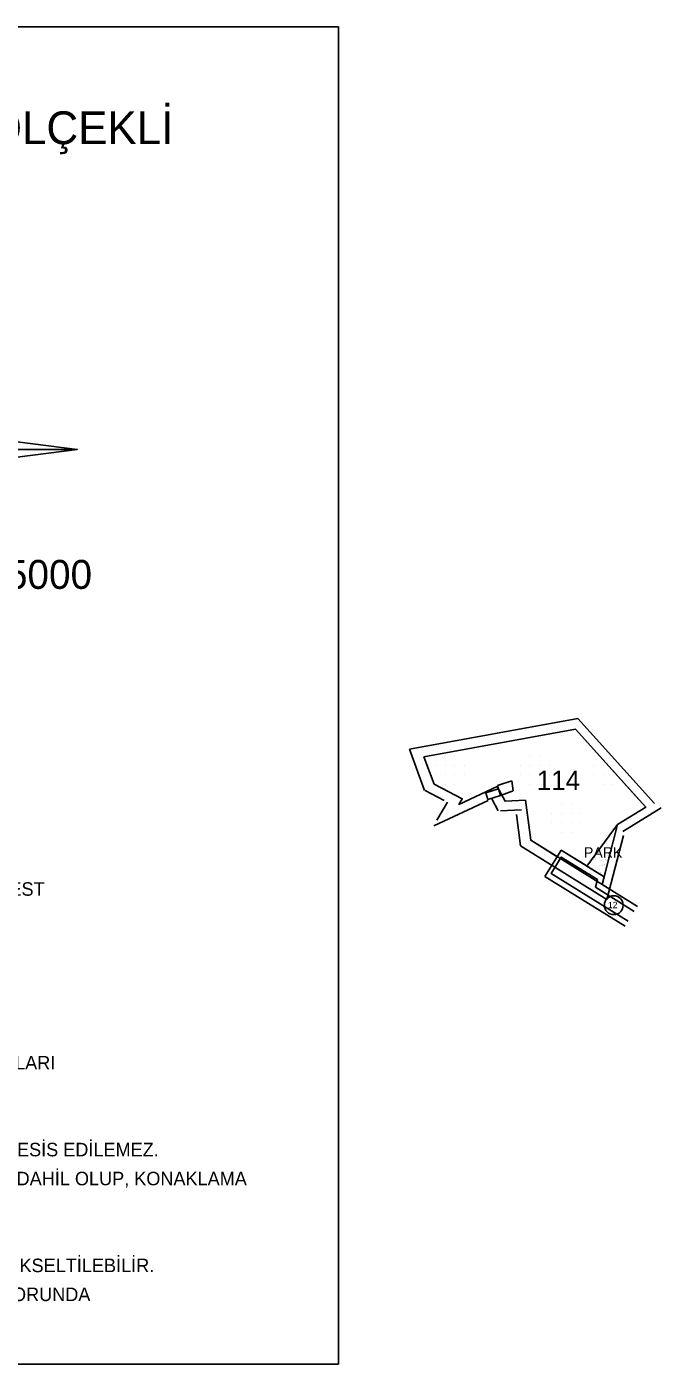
# Model space of a CAD drawing. Extents: x 415376 to 421084, y 4391163 to 4393878.
# Drawn here: x 417511 to 417839, y 4392614 to 4393307 of the extents above; entities that cross this region are included whole.
import ezdxf

# ---------------------------------------------------------------- set-up
doc = ezdxf.new("R2010")
doc.units = 0
for name, color, linetype in [('ADAKENARII', 7, 'Continuous'), ('ADAYRIMM', 7, 'Continuous'), ('KALDIRIM', 7, 'Continuous'), ('KDS_BİNA', 7, 'Continuous'), ('KDS_PARSEL', 7, 'Continuous'), ('KDS_PARSEL_NO', 7, 'Continuous'), ('LEJAND', 7, 'Continuous'), ('PL_KiRSALTURIZM', 7, 'Continuous'), ('PL_PARK', 7, 'Continuous'), ('SN_PLAN_ONAMA', 7, 'Continuous'), ('TR_PARK', 7, 'Continuous'), ('TR_TURIZM', 7, 'Continuous')]:
    doc.layers.add(name, color=color, linetype=linetype)

msp = doc.modelspace()

# ---------------------------------------------------------------- linework, layer by layer
at = {"layer": 'ADAKENARII'}
for p, q in [((417785.91, 4392877.51), (417779.06, 4392866.5)), ((417787.51, 4392880.09), (417785.91, 4392877.51)), ((417809.67, 4392866.31), (417787.51, 4392880.09)), ((417779.06, 4392866.5), (417820.57, 4392840.69)), ((417808.62, 4392862.25), (417809.67, 4392866.31)), ((417826.91, 4392850.88), (417808.62, 4392862.25))]:
    msp.add_line(p, q, dxfattribs=at)
at = {"layer": 'ADAYRIMM'}
for p, q in [((417831.32, 4392902.41), (417826.15, 4392908.13)), ((417816.67, 4392893.42), (417831.32, 4392902.41)), ((417816.67, 4392893.42), (417800.77, 4392871.84)), ((417809.67, 4392866.31), (417816.67, 4392893.42)), ((417784.45, 4392877.28), (417785.4, 4392876.69))]:
    msp.add_line(p, q, dxfattribs=at)
msp.add_lwpolyline([(417784.45, 4392877.28), (417771.71, 4392885.2), (417768.99, 4392905.94), (417758.52, 4392905.41), (417754.42, 4392913.01), (417734.58, 4392903.83), (417736.28, 4392906.74), (417721.72, 4392914.35), (417716.44, 4392928.36), (417794.85, 4392942.72), (417826.15, 4392908.13)], dxfattribs=at)
at = {"layer": 'KALDIRIM'}
msp.add_lwpolyline([(417825.33, 4392848.33), (417805.16, 4392860.87), (417806.21, 4392864.92), (417787.52, 4392876.54), (417782.24, 4392868.05), (417822.16, 4392843.23)], dxfattribs=at)
msp.add_circle((417814.69, 4392851.58), 4.87, dxfattribs=at)
at = {"layer": 'KDS_BİNA'}
for p, q in [((417754.55, 4392913.6), (417761.98, 4392915.96)), ((417755.07, 4392911.8), (417754.55, 4392913.6)), ((417761.98, 4392915.96), (417762.62, 4392910.81)), ((417755.06, 4392911.84), (417748.47, 4392909.78)), ((417748.47, 4392909.78), (417749.55, 4392906.35)), ((417749.55, 4392906.35), (417756.14, 4392908.44)), ((417756.14, 4392908.44), (417755.06, 4392911.84)), ((417762.62, 4392910.81), (417756.14, 4392908.44))]:
    msp.add_line(p, q, dxfattribs=at)
at = {"layer": 'KDS_PARSEL'}
for p, q in [((417794.85, 4392942.72), (417716.44, 4392928.36)), ((417831.32, 4392902.41), (417794.85, 4392942.72)), ((417716.44, 4392928.36), (417721.72, 4392914.35)), ((417721.72, 4392914.35), (417736.28, 4392906.74)), ((417734.58, 4392903.83), (417754.42, 4392913.01)), ((417754.42, 4392913.01), (417758.52, 4392905.41)), ((417736.28, 4392906.74), (417734.58, 4392903.83)), ((417758.52, 4392905.41), (417768.99, 4392905.94)), ((417768.99, 4392905.94), (417771.71, 4392885.2)), ((417816.67, 4392893.42), (417831.32, 4392902.41)), ((417808.62, 4392862.25), (417816.67, 4392893.42)), ((417771.71, 4392885.2), (417808.62, 4392862.25))]:
    msp.add_line(p, q, dxfattribs=at)
at = {"layer": 'LEJAND'}
for p, q in [((417672.31, 4393306.66), (416870.43, 4393306.66)), ((417672.31, 4392613.77), (417672.31, 4393306.66)), ((417483.55, 4393087.66), (417537.07, 4393087.66)), ((416870.43, 4392613.77), (417672.31, 4392613.77))]:
    msp.add_line(p, q, dxfattribs=at)
for points in [[(417489.64, 4393093.76), (417483.55, 4393141.18), (417477.45, 4393093.76), (417430.02, 4393087.66), (417477.45, 4393081.56), (417483.55, 4393034.14), (417489.64, 4393081.56), (417537.07, 4393087.66)], [(417483.55, 4393087.66), (417489.64, 4393081.56), (417537.07, 4393087.66)]]:
    msp.add_lwpolyline(points, close=True, dxfattribs=at)
at = {"layer": 'PL_KiRSALTURIZM'}
msp.add_lwpolyline([(417785.91, 4392877.51), (417787.51, 4392880.09), (417799.83, 4392872.43), (417800.77, 4392871.84), (417816.67, 4392893.42), (417831.32, 4392902.41), (417826.15, 4392908.13), (417794.85, 4392942.72), (417716.44, 4392928.36), (417721.72, 4392914.35), (417736.28, 4392906.74), (417734.58, 4392903.83), (417754.42, 4392913.01), (417758.52, 4392905.41), (417768.99, 4392905.94), (417771.71, 4392885.2), (417784.45, 4392877.28), (417785.4, 4392876.69), (417785.91, 4392877.51)], dxfattribs=at)
at = {"layer": 'PL_PARK'}
msp.add_lwpolyline([(417800.77, 4392871.84), (417809.67, 4392866.31), (417816.67, 4392893.42), (417800.77, 4392871.84)], dxfattribs=at)
at = {"layer": 'SN_PLAN_ONAMA'}
for p, q in [((417796.03, 4392948.29), (417708.99, 4392932.35)), ((417835.8, 4392904.33), (417796.03, 4392948.29)), ((417708.99, 4392932.35), (417716.84, 4392911.07)), ((417717.06, 4392910.95), (417726.87, 4392905.82)), ((417721.58, 4392892.76), (417749.73, 4392905.78)), ((417751.6, 4392906.64), (417754.96, 4392900.4)), ((417728.66, 4392904.88), (417723.21, 4392895.55)), ((417756.15, 4392900.46), (417767.02, 4392901.01)), ((417764.29, 4392898.49), (417766.4, 4392882.35)), ((417819.32, 4392889.73), (417839.25, 4392901.96)), ((417811.1, 4392854.56), (417819.65, 4392887.67)), ((417766.4, 4392882.35), (417811.1, 4392854.56))]:
    msp.add_line(p, q, dxfattribs=at)
at = {"layer": 'TR_PARK'}
for p, q in [((417815.66, 4392891.56), (417815.66, 4392891.56)), ((417817.06, 4392893.79), (417817.06, 4392893.79)), ((417817.06, 4392893.79), (417817.06, 4392893.79)), ((417817.06, 4392893.79), (417817.06, 4392893.79)), ((417811.12, 4392884.52), (417811.12, 4392884.52)), ((417811.92, 4392886.95), (417811.92, 4392886.95)), ((417812.52, 4392886.75), (417812.52, 4392886.75)), ((417812.52, 4392886.75), (417812.52, 4392886.75)), ((417812.52, 4392886.75), (417812.52, 4392886.75)), ((417812.54, 4392884.52), (417812.54, 4392884.52)), ((417812.54, 4392884.52), (417812.54, 4392884.52)), ((417813.38, 4392889.03), (417813.38, 4392889.03)), ((417813.38, 4392889.03), (417813.38, 4392889.03)), ((417813.38, 4392889.03), (417813.38, 4392889.03)), ((417813.69, 4392887.37), (417813.69, 4392887.37)), ((417813.69, 4392887.37), (417813.69, 4392887.37)), ((417813.69, 4392887.37), (417813.69, 4392887.37)), ((417815.66, 4392890.82), (417815.66, 4392890.82)), ((417815.66, 4392890.82), (417815.66, 4392890.82)), ((417815.66, 4392890.82), (417815.66, 4392890.82)), ((417807.05, 4392879.7), (417807.05, 4392879.7)), ((417807.05, 4392878.95), (417807.05, 4392878.95)), ((417807.05, 4392878.95), (417807.05, 4392878.95)), ((417807.05, 4392878.95), (417807.05, 4392878.95)), ((417808.45, 4392881.92), (417808.45, 4392881.92)), ((417808.45, 4392881.92), (417808.45, 4392881.92)), ((417808.45, 4392881.92), (417808.45, 4392881.92)), ((417808.46, 4392879.7), (417808.46, 4392879.7)), ((417808.46, 4392879.7), (417808.46, 4392879.7)), ((417808.84, 4392881.99), (417808.84, 4392881.99)), ((417808.84, 4392881.99), (417808.84, 4392881.99)), ((417808.84, 4392881.99), (417808.84, 4392881.99)), ((417809.15, 4392880.33), (417809.15, 4392880.33)), ((417809.15, 4392880.33), (417809.15, 4392880.33)), ((417809.15, 4392880.33), (417809.15, 4392880.33)), ((417809.79, 4392878.29), (417809.79, 4392878.29)), ((417809.79, 4392878.29), (417809.79, 4392878.29)), ((417809.79, 4392878.29), (417809.79, 4392878.29)), ((417809.96, 4392884.13), (417809.96, 4392884.13)), ((417809.96, 4392884.13), (417809.96, 4392884.13)), ((417810.56, 4392880.33), (417810.56, 4392880.33)), ((417810.56, 4392880.33), (417810.56, 4392880.33)), ((417810.56, 4392880.33), (417810.56, 4392880.33)), ((417810.74, 4392878.72), (417810.74, 4392878.72)), ((417811.12, 4392883.78), (417811.12, 4392883.78)), ((417811.12, 4392883.78), (417811.12, 4392883.78)), ((417811.12, 4392883.78), (417811.12, 4392883.78)), ((417811.83, 4392881.12), (417811.83, 4392881.12)), ((417811.83, 4392881.12), (417811.83, 4392881.12)), ((417811.83, 4392881.12), (417811.83, 4392881.12)), ((417811.83, 4392881.12), (417811.83, 4392881.12)), ((417812.05, 4392878.95), (417812.05, 4392878.95)), ((417812.54, 4392879.52), (417812.54, 4392879.52)), ((417812.54, 4392879.52), (417812.54, 4392879.52)), ((417812.54, 4392879.52), (417812.54, 4392879.52)), ((417812.54, 4392879.52), (417812.54, 4392879.52)), ((417812.85, 4392882.12), (417812.85, 4392882.12)), ((417812.85, 4392882.12), (417812.85, 4392882.12)), ((417812.85, 4392882.12), (417812.85, 4392882.12)), ((417801.71, 4392873.33), (417801.71, 4392873.33)), ((417801.71, 4392873.33), (417801.71, 4392873.33)), ((417801.71, 4392873.33), (417801.71, 4392873.33)), ((417802.02, 4392871.67), (417802.02, 4392871.67)), ((417802.02, 4392871.67), (417802.02, 4392871.67)), ((417802.02, 4392871.67), (417802.02, 4392871.67)), ((417804, 4392875.87), (417804, 4392875.87)), ((417804, 4392875.13), (417804, 4392875.13)), ((417804, 4392875.13), (417804, 4392875.13)), ((417804, 4392875.13), (417804, 4392875.13)), ((417804.76, 4392877.16), (417804.76, 4392877.16)), ((417804.76, 4392877.16), (417804.76, 4392877.16)), ((417804.76, 4392877.16), (417804.76, 4392877.16)), ((417805.08, 4392875.5), (417805.08, 4392875.5)), ((417805.08, 4392875.5), (417805.08, 4392875.5)), ((417805.08, 4392875.5), (417805.08, 4392875.5)), ((417805.41, 4392875.87), (417805.41, 4392875.87)), ((417805.41, 4392875.87), (417805.41, 4392875.87)), ((417805.41, 4392870.87), (417805.41, 4392870.87)), ((417805.41, 4392870.87), (417805.41, 4392870.87)), ((417805.41, 4392870.87), (417805.41, 4392870.87)), ((417805.41, 4392870.87), (417805.41, 4392870.87)), ((417806.35, 4392871.29), (417806.35, 4392871.29)), ((417806.35, 4392871.29), (417806.35, 4392871.29)), ((417807.37, 4392872.29), (417807.37, 4392872.29)), ((417807.37, 4392872.29), (417807.37, 4392872.29)), ((417807.51, 4392876.5), (417807.51, 4392876.5)), ((417807.51, 4392876.5), (417807.51, 4392876.5)), ((417807.51, 4392876.5), (417807.51, 4392876.5)), ((417807.68, 4392874.89), (417807.68, 4392874.89)), ((417808.46, 4392874.7), (417808.46, 4392874.7)), ((417808.46, 4392874.7), (417808.46, 4392874.7)), ((417808.46, 4392874.7), (417808.46, 4392874.7)), ((417808.46, 4392874.7), (417808.46, 4392874.7)), ((417808.54, 4392872.37), (417808.54, 4392872.37)), ((417808.54, 4392872.37), (417808.54, 4392872.37)), ((417808.68, 4392872.53), (417808.68, 4392872.53)), ((417808.78, 4392877.29), (417808.78, 4392877.29)), ((417808.78, 4392877.29), (417808.78, 4392877.29)), ((417808.78, 4392877.29), (417808.78, 4392877.29)), ((417808.78, 4392877.29), (417808.78, 4392877.29)), ((417808.78, 4392872.29), (417808.78, 4392872.29)), ((417808.78, 4392872.29), (417808.78, 4392872.29)), ((417809, 4392875.13), (417809, 4392875.13)), ((417809.38, 4392874.42), (417809.38, 4392874.42)), ((417809.7, 4392872.76), (417809.7, 4392872.76)), ((417809.7, 4392872.02), (417809.7, 4392872.02)), ((417809.7, 4392872.02), (417809.7, 4392872.02)), ((417809.7, 4392872.02), (417809.7, 4392872.02)), ((417809.94, 4392872.68), (417809.94, 4392872.68)), ((417810.42, 4392876.12), (417810.42, 4392876.12)), ((417810.42, 4392876.12), (417810.42, 4392876.12)), ((417810.42, 4392876.12), (417810.42, 4392876.12)), ((417810.5, 4392875.19), (417810.5, 4392875.19)), ((417811.02, 4392872.31), (417811.02, 4392872.31)), ((417811.02, 4392872.31), (417811.02, 4392872.31)), ((417811.02, 4392872.31), (417811.02, 4392872.31)), ((417811.1, 4392874.99), (417811.1, 4392874.99)), ((417811.1, 4392874.99), (417811.1, 4392874.99)), ((417811.1, 4392874.99), (417811.1, 4392874.99)), ((417811.11, 4392872.76), (417811.11, 4392872.76)), ((417811.11, 4392872.76), (417811.11, 4392872.76)), ((417811.44, 4392877.12), (417811.44, 4392877.12)), ((417811.74, 4392876.36), (417811.74, 4392876.36)), ((417811.83, 4392876.12), (417811.83, 4392876.12)), ((417811.83, 4392876.12), (417811.83, 4392876.12)), ((417807.41, 4392870.23), (417807.41, 4392870.23)), ((417807.41, 4392870.23), (417807.41, 4392870.23)), ((417807.41, 4392870.23), (417807.41, 4392870.23)), ((417807.73, 4392868.57), (417807.73, 4392868.57)), ((417807.73, 4392868.57), (417807.73, 4392868.57)), ((417807.73, 4392868.57), (417807.73, 4392868.57)), ((417807.96, 4392868.49), (417807.96, 4392868.49)), ((417807.96, 4392868.49), (417807.96, 4392868.49)), ((417807.96, 4392868.49), (417807.96, 4392868.49)), ((417809, 4392864.36), (417809, 4392864.36)), ((417809, 4392864.36), (417809, 4392864.36))]:
    msp.add_line(p, q, dxfattribs=at)
at = {"layer": 'TR_TURIZM'}
for p, q in [((417787.65, 4392939.51), (417787.65, 4392939.51)), ((417792.65, 4392939.51), (417792.65, 4392939.51)), ((417727.48, 4392929.13), (417727.48, 4392929.13)), ((417732.48, 4392929.13), (417732.48, 4392929.13)), ((417771.29, 4392929.13), (417771.29, 4392929.13)), ((417776.29, 4392929.13), (417776.29, 4392929.13)), ((417722.48, 4392924.13), (417722.48, 4392924.13)), ((417722.48, 4392919.13), (417722.48, 4392919.13)), ((417727.48, 4392924.13), (417727.48, 4392924.13)), ((417727.48, 4392919.13), (417727.48, 4392919.13)), ((417732.48, 4392924.13), (417732.48, 4392924.13)), ((417732.48, 4392919.13), (417732.48, 4392919.13)), ((417737.48, 4392924.13), (417737.48, 4392924.13)), ((417737.48, 4392919.13), (417737.48, 4392919.13)), ((417766.29, 4392924.13), (417766.29, 4392924.13)), ((417766.29, 4392919.13), (417766.29, 4392919.13)), ((417771.29, 4392924.13), (417771.29, 4392924.13)), ((417771.29, 4392919.13), (417771.29, 4392919.13)), ((417776.29, 4392924.13), (417776.29, 4392924.13)), ((417776.29, 4392919.13), (417776.29, 4392919.13)), ((417781.29, 4392924.13), (417781.29, 4392924.13)), ((417781.29, 4392919.13), (417781.29, 4392919.13)), ((417804.3, 4392924.13), (417804.3, 4392924.13)), ((417804.3, 4392919.13), (417804.3, 4392919.13)), ((417809.3, 4392924.13), (417809.3, 4392924.13)), ((417809.3, 4392919.13), (417809.3, 4392919.13)), ((417814.3, 4392919.13), (417814.3, 4392919.13)), ((417727.48, 4392914.13), (417727.48, 4392914.13)), ((417732.48, 4392914.13), (417732.48, 4392914.13)), ((417771.29, 4392914.13), (417771.29, 4392914.13)), ((417776.29, 4392914.13), (417776.29, 4392914.13)), ((417809.3, 4392914.13), (417809.3, 4392914.13)), ((417814.3, 4392914.13), (417814.3, 4392914.13)), ((417782.65, 4392899.29), (417782.65, 4392899.29)), ((417787.65, 4392904.29), (417787.65, 4392904.29)), ((417787.65, 4392899.29), (417787.65, 4392899.29)), ((417792.65, 4392904.29), (417792.65, 4392904.29)), ((417792.65, 4392899.29), (417792.65, 4392899.29)), ((417797.65, 4392899.29), (417797.65, 4392899.29)), ((417782.65, 4392894.29), (417782.65, 4392894.29)), ((417787.65, 4392894.29), (417787.65, 4392894.29)), ((417792.65, 4392894.29), (417792.65, 4392894.29)), ((417797.65, 4392894.29), (417797.65, 4392894.29)), ((417787.65, 4392889.29), (417787.65, 4392889.29)), ((417792.65, 4392889.29), (417792.65, 4392889.29))]:
    msp.add_line(p, q, dxfattribs=at)

# ---------------------------------------------------------------- texts
at = {"layer": 'KALDIRIM'}
msp.add_text('12', height=3.28, dxfattribs=at).set_placement((417811.7, 4392850.04))
at = {"layer": 'KDS_PARSEL_NO'}
msp.add_text('114', height=10, dxfattribs=at).set_placement((417774.89, 4392911.27))
at = {"layer": 'LEJAND'}
for s, height, p in [('114 PARSEL, (KIRSAL) TURİZM ALANI AMAÇLI 1/5.000 ÖLÇEKLİ', 17, (416904.57, 4393245.84)), ('ÖLÇEK: 1/5000', 15, (417404.26, 4393015.45)), ('PARK', 5.468, (417799.26, 4392876.15)), ('KLİMATİZM ETKİNLİĞİ, AT İLE GEZİNTİETKİNLİĞİ, DAĞBİSİKLETİETKİNLİĞİDAĞCILIK ETKİNLİĞİ, DOĞADA SERBEST', 7, (417005.77, 4392856.48)), (' PLANLAMA ALANINDA; KIRSAL TURİZME YÖNELİK ÇİFTLİK-KÖY EVİ, YAYLA EVİ, DAĞ EVLERİ, HOBİT EVLERİ VB KONAKLAMA KULLANIMLARI ', 7, (416889.52, 4392766.48)), (' KONAKLAMA BİRİMLERİNDE YAPILACAK TESİSTE TAK BAĞIMSIZ BÖLÜM OLUŞTURULACAK OLUP, KAT MÜLKİYETİ VEYA KAT İRTİFAKI TESİS EDİLEMEZ. ', 7, (416889.52, 4392721.48)), ('’ DİR. TİCARİBİRİMLER EMSALE DAHİL OLUP, KONAKLAMA ', 7, (417361.62, 4392706.48)), ('RESTORAN YAPISI ESKİDEĞİRMEN İLE BİRLİKTE PROJELENDİRİLECEK OLUP SADECE BU ALANDA SU BASMAN KOTU  +-3 M. KADAR YÜKSELTİLEBİLİR.', 7, (416892.1, 4392661.48)), ('ÇEVRE VE ŞEHİRCİLİK İL MÜDÜRLÜĞÜ’NCE 12.02.2020 TARİHİNDE ONAYLANAN İMAR PLANINA ESAS JEOLOJİK- JEOTEKNİK ETÜD RAPORUNDA ', 7, (416892.1, 4392646.48))]:
    msp.add_text(s, height=height, dxfattribs=at).set_placement(p)

doc.saveas('drawing.dxf')
